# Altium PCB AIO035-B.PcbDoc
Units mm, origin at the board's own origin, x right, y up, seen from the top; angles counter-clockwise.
Board outline 100.5 x 55.66 mm, 2 copper layers (TopLayer, BottomLayer); 16 components, 10 nets, 94 pads, 78 vias.
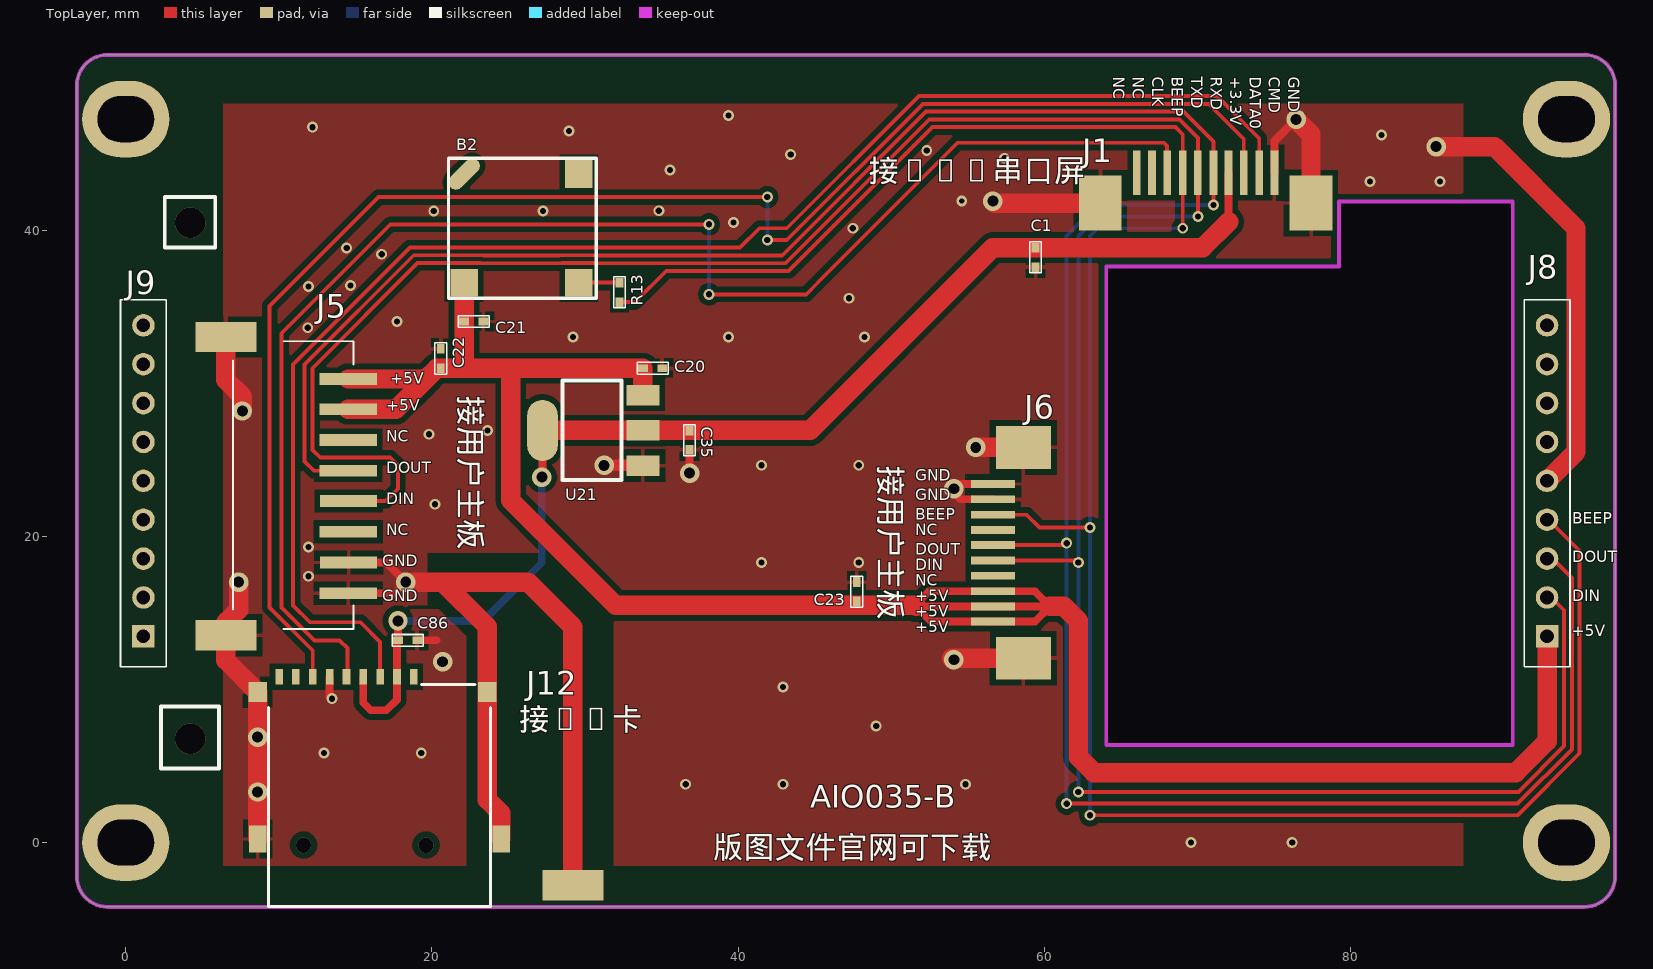
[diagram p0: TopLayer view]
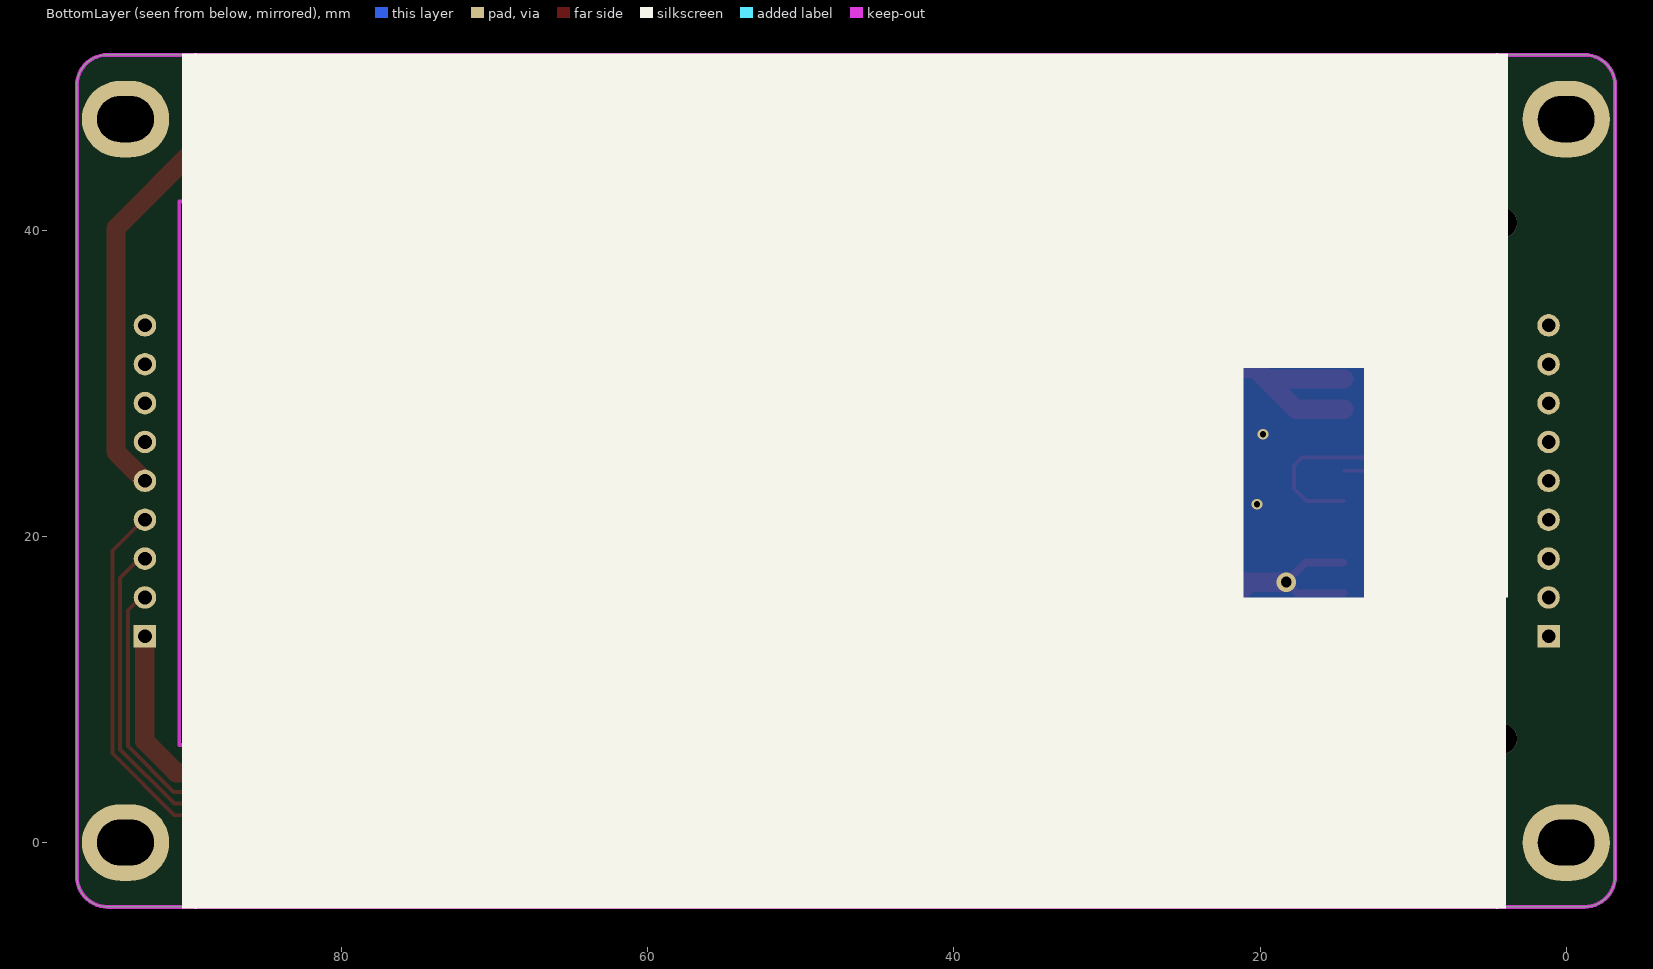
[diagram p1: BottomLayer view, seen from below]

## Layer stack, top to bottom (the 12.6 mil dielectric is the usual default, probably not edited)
TopLayer: signal copper 0.0356
Dielectric: dielectric 0.32, FR-4, Dk 4.8
BottomLayer: signal copper 0.0356

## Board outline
-1.2,-4.2 cw(c-1.2,-2.2) -3.2,-2.2 -3.2,49.46 cw(c-1.2,49.46) -1.2,51.46 95.3,51.46 cw(c95.3,49.46) 97.3,49.46 97.3,-2.2 cw(c95.3,-2.2) 95.3,-4.2
cut-out: 64.05,6.367 90.613,6.367 90.613,41.88 84.582,41.88 79.248,41.88 79.248,37.639 64.05,37.64

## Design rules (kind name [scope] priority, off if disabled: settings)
Clearance Clearance_polygon [InPolygon] p1: gap=0.381
Clearance [All] p2: gap=0.254
FabricationTestPointUsage TestPointUsage [All] p1: valid=0 allowmultiple=FALSE
FabricationTestpoint Testpoint [All] p1: side=3 testpointundercomponent=TRUE minsize=1.016 maxsize=2.54 preferedsize=1.524 minholesize=0.508 maxholesize=1.016 preferedholesize=0.813 testpointgrid=0.025 allowsidetop=TRUE allowsidebottom=TRUE usegrid=TRUE gridtolerance=0
HoleSize [All] p1: absolutevalues=TRUE maxlimit=7.62 minlimit=0.025 maxpercent=80.000 minpercent=20.000
PolygonConnect PolygonConnect_1 [IsPoly vs InComponent('B2','C1','C20','C21','C22','C23','C35','C86','J1','J12','J5','J6','J8','J9','R13','U21')] p1: connectstyle=Relief reliefconductorwidth=0.254 reliefentries=4 polygonreliefangle="90 Angle"
PolygonConnect [All] p2: connectstyle=Direct reliefconductorwidth=0.254 reliefentries=4 polygonreliefangle="90 Angle"
RoutingVias [All] p1: holewidth=0.711 width=1.27 viastyle="Through Hole" minholewidth=0.711 minwidth=1.27 maxholewidth=0.711 maxwidth=1.27
SilkToSilkClearance [All] p1: silktosilkclearance=0
SilkscreenOverComponentPads [All] p1: minsilkscreentomaskgap=0
SolderMaskExpansion [All] p1: expansion=0.102
Width [All] p1: maxlimit=1.27 minlimit=0.152 preferedwidth=0.508 minimp=50.000000 maximp=50.000000 favimp=50.000000
23 further rules are at their usual default settings.

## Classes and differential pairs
component class AIO035-B: B2 C1 C20 C21 C22 C23 C35 C86 J1 J5 J6 J8 J12 R13 U21

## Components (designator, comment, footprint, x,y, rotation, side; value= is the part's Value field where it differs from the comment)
B2 "KLJ-8530" BEEP 22.098,36.576 r0 top locked
C1 "4.7uF/6.3V" 0402A 59.436,38.862 r270 top
C20 "4.7uF/6.3V" 0402A 33.782,30.988 r0 top
C21 "4.7uF/6.3V" 0402A 22.098,34.036 r0 top
C22 "4.7uF/6.3V" 0402A 20.574,30.988 r90 top
C23 "4.7uF/6.3V" 0402A 47.752,15.748 r90 top
C35 "4.7uF/6.3V" 0402A 36.83,26.924 r270 top
C86 "4.7uF/6.3V" 0402A 17.78,13.208 r0 top
J1 "FPC1.0-10下接" FPC1.0-10下接 66.05,43.76 r0 top locked
J5 "FPC2.0-8卧贴-带锁扣" FPC2.0-8卧贴-带锁扣 14.532,16.288 r270 top locked
J6 "FPC1.0-10下接" FPC1.0-10下接 56.658,14.432 r90 top locked
J8 "2.54-9-DIP" 2.54-9-DIP 92.85,13.47 r0 top
J9 "2.54-9-DIP" 2.54-9-DIP 1.15,13.47 r0 top (schematic designator J8)
J12 "TF卡" TF卡 18.812,10.83 r0 top locked
R13 "62R" 0402A 32.258,36.576 r270 top
U21 "AMS1117-3.3" AMS1117-3.3 33.782,26.924 r90 top locked

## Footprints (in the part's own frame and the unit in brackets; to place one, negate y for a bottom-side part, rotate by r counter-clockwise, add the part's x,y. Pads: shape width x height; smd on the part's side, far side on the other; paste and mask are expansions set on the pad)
2.54-9-DIP [mil]
  rect 58x58 hole 35: 1(0,0)
  round 58 hole 35: 2(0,100) 3(0,200) 4(0,300) 5(0,400) 6(0,500) 7(0,600) 8(0,700) 9(0,800)
  silkscreen extent -59,-79 59,866
0402A [mil]
  rect 25x20 smd: 1(0,0) 2(50,0)
  silkscreen extent -15,-15 65,15
AMS1117-3.3 [mm]
  rect 1.35x2.15 smd: 1(-2.3,0) 2(0,0) 3(2.3,0)
  oval 4x2 smd: 4(0,6.56)
  silkscreen extent -3.25,1.4 3.25,5.25
BEEP [mm]
  rect 1.8x1.8 smd: 1(0,0) 2(7.5,0) 3(7.5,7.1)
  oval 2.5x1 smd rot 45: 4(0,7.1)
  silkscreen extent -1.02,-1.02 8.64,8.13
FPC1.0-10下接 [mil]
  rect 20x114 smd: 1(0,0) 2(39,0) 3(78,0) 4(118,0) 5(157,0) 6(197,0) 7(236,0) 8(275,0) 9(315,0) 10(354,0)
  rect 110x142 smd: 11(-94,-78) 12(448,-78)
FPC2.0-8卧贴-带锁扣 [mil]
  rect 30x147 smd: 1(0,0) 2(-79,1) 3(-158,0) 4(-237,1) 5(-315,0) 6(-394,0) 7(-473,0) 8(-551,0)
  rect 78x157 smd: 9(108,-315) 10(-659,-315)
  silkscreen extent -648,-297 92,13
TF卡 [mm]
  rect 0.5x1 smd: 1(0,0) 2(-1.1,0) 3(-2.2,0) 4(-3.3,0) 5(-4.4,0) 6(-5.5,0) 7(-6.6,0) 8(-7.7,0) 9(-8.8,0)
  rect 1.2x1.3 smd: 10(4.8,-1) 11(-10.2,-1)
  rect 1.143x1.778 smd: 12(5.7,-10.6) 13(-10.2,-10.6)
  silkscreen extent -9.5,-15 5,-0.5

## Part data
B2: library part BEEP
C1 C21 C22 C23: library part C
C20 C35 C86: library part CAP, "Cap"
J12: library part TF?
R13: library part RES1

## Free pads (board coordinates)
  rect 4x2 smd: 1(29.21,-2.794)
  oval 5.7x5 hole 3 slot 3.7 at 0 deg: 9(0,0) 9(0,47.26) 9(94.12,47.26) 10(94.12,0)

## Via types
v1: diameter 0.711, hole 0.406, TopLayer to BottomLayer, 57 vias
v2: diameter 1.27, hole 0.711, TopLayer to BottomLayer, 16 vias
v3: diameter 1, hole 1, TopLayer to BottomLayer, 2 vias
v4: diameter 2, hole 2, TopLayer to BottomLayer, 2 vias
v5: diameter 0.711, hole 0.356, TopLayer to BottomLayer, 1 vias

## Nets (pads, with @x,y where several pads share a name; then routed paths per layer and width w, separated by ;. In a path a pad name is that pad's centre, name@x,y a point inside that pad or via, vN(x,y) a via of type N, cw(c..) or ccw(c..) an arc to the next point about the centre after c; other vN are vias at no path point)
3.3V: C1.1 C35.1 C86.1 J1.7 J12.2 J12.4 U21.2 U21.4 | length 82.9
  TopLayer w0.508: J12.4 15.512,9.126 16.002,8.636 17.018,8.636 17.712,9.33 J12.2 17.712,13.14 C86.1 v2(17.78,14.478) ; v2(27.178,23.876) 27.222,23.92 U21.4 ; 72.044,40.548 J1.7
  TopLayer w1.27: U21.4 U21.2 44.704,26.924 56.642,38.862 C1.1 70.358,38.862 72.044,40.548
  BottomLayer w0.508: v2(17.78,14.478) 23.368,14.478 27.178,18.288 v2(27.178,23.876)
5V: B2.1 C20.1 C21.1 C22.1 C23.1 J5.7 J5.8 J6.1 J6.2 J6.3 J8.1 U21.3 | length 148.3
  TopLayer w0.508: 51.562,15.494 52.481,16.413 J6.3 59.39,16.413 60.381,15.423 ; 60.381,15.423 59.39,14.432 J6.1 52.624,14.432 51.633,15.423 J6.2 60.381,15.423
  TopLayer w1.27: J5.7 17.634,28.302 19.615,30.283 ; J5.8 19.615,30.283 ; B2.1 C21.1 22.098,30.988 ; U21.3@33.782,29.478 C20.1 25.146,30.988 ; 51.633,15.423 51.562,15.494 33.782,15.494 32.004,15.494 25.146,22.352 25.146,30.988 ; 60.381,15.423 61.285,15.423 62.23,14.478 62.23,5.588 63.246,4.572 90.809,4.572 92.85,6.613 J8.1 ; 19.615,30.283 20.32,30.988 C22.1 22.098,30.988 ; 22.098,30.988 25.146,30.988
BEEP: J1.4 J6.8 J8.4 R13.2 | length 148.3
  TopLayer w0.254: R13.2 33.274,35.306 35.306,37.338 43.303,37.338 52.701,46.736 68.58,46.736 69.047,46.269 J1.4 v1@69.047,40.386 ; J6.8 58.847,21.417 59.69,20.574 v1(62.992,20.574) ; v1(62.992,1.778) 90.932,1.778 94.984,5.83 94.984,19.062 92.956,21.09 J8.4
  BottomLayer w0.254: v1(62.992,1.778) v1(62.992,20.574) 62.992,39.624 63.5,40.132 v1(69.047,40.132)
CLK: J1.3 J12.5 | length 96.3
  TopLayer w0.254: J12.5 14.412,11.019 14.478,11.085 14.478,12.7 13.97,13.208 12.319,13.208 10.16,15.367 10.16,33.274 17.272,40.386 v1(38.1,40.386) ; v1(38.1,35.814) 44.45,35.814 45.237,36.601 45.237,36.627 54.33,45.72 67.818,45.72 68.031,45.507 J1.3
  BottomLayer w0.254: v1@38.1,36.068 v1(38.1,40.386)
CMD: J1.9 J12.3 | length 98.5
  TopLayer w0.254: J12.3 16.612,13.106 15.326,14.392 12.024,14.392 10.922,15.494 10.922,31.242 18.553,38.873 23.577,38.873 23.588,38.862 28.108,38.862 28.119,38.873 31.077,38.873 31.088,38.862 40.132,38.862 41.402,40.132 43.18,40.132 51.816,48.768 71.283,48.768 74.051,46 J1.9
DAT0: J1.8 J12.7 | length 101.6
  TopLayer w0.254: J12.7@12.192,10.81 J12.7 12.212,12.553 9.398,15.367 9.398,35.052 16.51,42.164 v1(41.91,42.164) ; v1(41.91,39.37) 43.18,39.37 52.07,48.26 70.749,48.26 73.035,45.974 J1.8
  BottomLayer w0.254: v1(41.91,39.37) v1(41.91,42.164)
GND: C1.2 C20.2 C21.2 C22.2 C23.2 C35.2 C86.2 J1.10 J1.11 J1.12 J5.1 J5.2 J5.9 J5.10 J6.9 J6.10 J6.11 J6.12 J8.5 J12.6 J12.10 J12.11 J12.12 J12.13 pad.1 U21.1 | length 145.5
  TopLayer w0.508: J5.9 J5.9@6.604,13.618 ; v1@13.312,9.548 J12.6 ; J5.1 17.558,16.288 v2(18.288,17.018) 17.011,18.295 J5.2 ; C86.2 20.32,13.208 ; v2(36.83,24.13) C35.2 ; v2@53.848,23.114 54.529,22.433 J6.9 ; v2@54.158,23.424 J6.10 ; v2(56.642,41.902) v2@56.765,41.779 ; J1.10 75.042,45.832 v2(76.454,47.244)
  TopLayer w0.762: v2(31.242,24.638) U21.1@33.768,24.638
  TopLayer w1.27: J5.10 6.531,30.226 7.62,29.137 v2(7.62,28.194) ; J5.9@6.604,13.618 J5.9@6.604,14.449 ; v2(7.366,17.018) 7.366,15.211 J5.9@6.604,14.449 ; J12.13 v2(8.612,3.302) v2(8.612,6.882) J12.11 6.531,11.911 J5.9 6.531,14.376 J5.9@6.604,14.449 ; v2(18.288,17.018) 20.701,17.018 ; J12.12 24.512,1.904 23.612,2.804 J12.10 23.612,14.107 20.701,17.018 ; pad.1 29.21,14.072 26.264,17.018 20.701,17.018 ; v2@53.954,12.044 J6.11 ; v2(55.529,25.811) J6.12 ; v2@56.765,41.779 J1.11 ; v2(76.454,47.244) 77.429,46.269 J1.12 ; v2(85.598,45.466) 89.408,45.466 94.742,40.132 94.742,25.522 J8.5
  other v1: 69.596,0 76.2,0 36.576,3.81 42.926,3.81 54.864,3.81 12.954,5.842 19.304,5.842 49.022,7.62 13.462,9.398 42.926,10.16 11.938,17.399 41.536,18.296 47.886,18.296 11.938,19.304 20.193,22.098 41.536,24.646 47.886,24.646 19.812,26.67 23.622,26.924 29.21,33.02 39.37,33.02 48.26,33.02 11.887,33.63 17.707,34.036 47.244,35.56 11.938,36.322 14.681,36.398 16.713,38.43 14.427,38.837 47.498,40.132 39.7,40.513 20.117,41.25 27.254,41.25 34.823,41.275 81.28,43.18 85.852,43.18 35.56,43.942 57.404,44.704 43.434,44.958 52.324,45.212 82.042,46.228 28.956,46.482 12.192,46.736 39.37,47.498
  other v2: 20.701,11.811 54.102,11.938 54.102,23.114
  other v5: 54.61,41.91
NetB2_2: B2.2 R13.1 | length 2.7
  TopLayer w0.254: B2.2 R13.1
RXD: J1.5 J5.4 J6.5 J8.2 | length 180.4
  TopLayer w0.254: J5.4 16.974,22.308 17.78,23.114 17.78,24.638 17.272,25.146 12.7,25.146 12.192,25.654 12.192,30.988 19.061,37.857 23.156,37.857 23.167,37.846 28.529,37.846 28.54,37.857 30.656,37.857 30.667,37.846 43.093,37.846 52.491,47.244 68.834,47.244 70.038,46.04 J1.5 v1@70.038,41.148 ; J6.5 62.098,18.42 v1(62.23,18.288) ; v1(62.23,3.302) 90.976,3.302 93.968,6.294 93.968,15.175 92.85,16.292 J8.2
  BottomLayer w0.254: v1(62.23,3.302) v1(62.23,18.288) 62.23,39.624 63.5,40.894 v1(70.038,40.894)
TXD: J1.6 J5.5 J6.6 J8.3 | length 180.8
  TopLayer w0.254: J5.5 12.287,24.289 11.684,24.892 11.684,31.242 18.807,38.365 23.366,38.365 23.377,38.354 28.319,38.354 28.33,38.365 30.866,38.365 30.877,38.354 42.882,38.354 52.28,47.752 69.088,47.752 71.054,45.786 J1.6 v1(71.054,41.656) ; J6.6 61.346,19.436 v1(61.468,19.558) ; v1(61.468,2.54) 90.932,2.54 94.476,6.084 94.476,17.284 93.21,18.55 J8.3
  BottomLayer w0.254: v1(61.468,2.54) v1(61.468,19.558) 61.468,39.624 63.5,41.656 v1(71.054,41.656)
pads on no net: B2.3 B2.4 J1.1 J1.2 J5.3 J5.6 J6.4 J6.7 J8.6 J8.7 J8.8 J8.9 J9.1 J9.2 J9.3 J9.4 J9.5 J9.6 J9.7 J9.8 J9.9 J12.1 J12.8 J12.9
copper on no net:
  other v3: 11.612,-0.17 19.612,-0.17
  other v4: 4.21,6.78 4.21,40.48

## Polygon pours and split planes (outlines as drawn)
GND on BottomLayer "TopLayer-No Net" (solid, remove dead copper, pour order 5): 6.35,48.26 6.35,-1.524 87.376,-1.524 87.376,48.26
GND on TopLayer "TopLayer-No Net" (solid, remove dead copper, pour order 6): 6.35,48.26 6.35,-1.524 22.225,-1.524 22.225,13.462 20.447,15.24 18.415,15.24 18.415,15.367 20.32,15.367 20.193,15.494 20.32,15.367 18.415,15.367 18.415,15.494 20.193,15.494 19.685,15.494 19.558,15.621 19.685,15.494 19.685,18.923 27.432,18.923 31.623,14.732 31.877,14.732 31.877,-1.524 87.376,-1.524 87.376,48.26 6.35,48.26

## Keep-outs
KeepOutLayer:
  lines w0.254: 79.248,41.01 79.248,41.01 ; 79.248,41.01 79.248,41.88 88.277,41.88 90.613,41.88 90.613,6.367 64.05,6.367 64.05,37.64 79.248,37.639 79.248,41.01 ; -3.2,-2.2 ccw(c-1.2,-2.2) -1.2,-4.2 95.3,-4.2 ccw(c95.3,-2.2) 97.3,-2.2 97.3,49.46 ccw(c95.3,49.46) 95.3,51.46 -1.2,51.46 ccw(c-1.2,49.46) -3.2,49.46 -3.2,-2.2

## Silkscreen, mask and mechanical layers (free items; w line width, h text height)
TopOverlay:
  lines w0.254: 2.286,4.826 6.096,4.826 6.096,8.89 2.286,8.89 2.286,4.826 ; 2.54,38.862 2.54,42.164 5.842,42.164 5.842,38.862 2.54,38.862
  text "NC" at 64.262,50.038 h1.27 r270
  text "NC" at 65.532,50.038 h1.27 r270
  text "CLK" at 66.802,50.038 h1.27 r270
  text "BEEP" at 68.072,50.038 h1.27 r270
  text "TXD" at 69.342,50.038 h1.27 r270
  text "RXD" at 70.612,50.038 h1.27 r270
  text "+3.3V" at 71.882,50.038 h1.27 r270
  text "DATA0" at 73.152,50.038 h1.27 r270
  text "CMD" at 74.422,50.038 h1.27 r270
  text "GND" at 75.692,50.038 h1.27 r270
  text "接AIO串口屏" at 48.514,42.672 h2.54
  text "+5V" at 17.272,29.718 h1.27
  text "接用户主板" at 21.336,29.21 h2.54 r270
  text "+5V" at 17.018,27.94 h1.27
  text "NC" at 17.018,25.908 h1.27
  text "接用户主板" at 48.768,24.638 h2.54 r270
  text "DOUT" at 17.018,23.876 h1.27
  text "GND" at 51.562,23.368 h1.27
  text "GND" at 51.562,22.098 h1.27
  text "DIN" at 17.018,21.844 h1.27
  text "BEEP" at 51.562,20.828 h1.27
  text "BEEP" at 94.488,20.574 h1.27
  text "NC" at 17.018,19.812 h1.27
  text "NC" at 51.562,19.812 h1.27
  text "DOUT" at 51.562,18.542 h1.27
  text "DOUT" at 94.488,18.034 h1.27
  text "GND" at 16.764,17.78 h1.27
  text "DIN" at 51.562,17.526 h1.27
  text "NC" at 51.562,16.51 h1.27
  text "GND" at 16.764,15.494 h1.27
  text "+5V" at 51.562,15.494 h1.27
  text "DIN" at 94.488,15.494 h1.27
  text "+5V" at 51.562,14.478 h1.27
  text "+5V" at 51.562,13.462 h1.27
  text "+5V" at 94.476,13.208 h1.27
  text "接TF卡" at 25.654,6.858 h2.54
  text "AIO035-B" at 44.704,1.778 h2.54
  text "版图文件官网可下载" at 38.354,-1.524 h2.54
BottomOverlay:
  rectangle: 21.082,-4.318 90.424,51.562
  rectangle: 3.81,30.988 21.082,51.562
  rectangle: 3.936,-4.318 21.208,16.002
  rectangle: 3.81,16.002 13.208,31.002
  lines w0.254: 4.51,-4.2 4.51,51.46 ; 89.55,-4.2 89.55,6.367 ; 89.55,41.88 89.55,51.46
BottomSolder:
  rectangle: 13.208,16.002 21.208,31.002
